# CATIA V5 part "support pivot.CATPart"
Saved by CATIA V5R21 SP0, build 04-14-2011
Part number: SupportPivot
Bounding box of the stored display mesh (mm): x -21 to 21, y -21 to 38, z 0 to 27
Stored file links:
  C:\Users\2027.DESARCY-LEMIE30\Desktop\V14(17.02.2023)\support pivot.CATPart
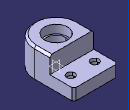
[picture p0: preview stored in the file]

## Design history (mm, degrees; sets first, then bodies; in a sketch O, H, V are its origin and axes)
Body1 (main body)
  Sketch1 on xy-plane, origin (0, 0, 0), H (1, 0, 0), V (0, 1, 0)
    arc A1 centre (0, 0) radius 21 from (-21, 0) to (21, 0) ccw
    line L1 (-21, 15) -> (21, 15)
    line L2 (21, 15) -> (21, 0)
    line L3 (-21, 0) -> (-21, 15)
    radius A1 = 21
    length L1 = 42
    distance L1 H = 15
    horizontal: L1 H
    vertical: L2 V, L3 V
  Pad1: profile Sketch1, direction (0, 0, 1), length 27
  Sketch2 on xy-plane, origin (0, 0, 0), H (1, 0, 0), V (0, 1, 0)
    line L1 (21, 0) -> (21, 38)
    line L2 (21, 38) -> (-21, 38)
    line L3 (-21, 38) -> (-21, 0)
    line L4 (-21, 0) -> (21, 0)
    distance L2 H = 38
    distance L1 V = 21
    length L2 = 42
    horizontal: L2 H, L4 H
    vertical: L1 V, L3 V
  Pad2: profile Sketch2, direction (0, 0, 1), length 11
  Sketch3 on end face of Pad1, origin (1.3571, -8.2844, 27), H (1, 0, 0), V (0, 1, 0)
    point P1 (-1.3571, 8.2844)
    reference projected arc E1 centre (-1.3571, 8.2844) radius 21 from (-22.3571, 8.2844) to (19.6429, 8.2844) ccw from edge [face of Pad1 from Sketch1.A1 | end face of Pad1]
    reference intersected line E2 through (-1.3571, 0) direction (0, 1) from yz-plane
    reference intersected line E3 through (0, 8.2844) direction (-1, 0) from zx-plane
    radius E1 = 21 (reference)
    distance P1 E2 = 0
    distance E3 P1 = 0
  Hole1: placed by Sketch3, at (0, 0, 27) direction (0, 0, -1), diameter 22, through (limit type 6)
  Sketch4 on face of Pad2, origin (-11.5216, 25.6596, 0), H (1, 0, 0), V (0, -1, 0)
    point P1 (0.0216, 0.1596)
    reference projected line E1 (-9.4784, 10.6596) -> (-9.4784, 25.6596) from edge [face of Pad2 | face of Pad2]
    reference projected line E2 (32.5216, -12.3404) -> (-9.4784, -12.3404) from edge [start face of Pad2 | face of Pad2 from Sketch2.L2]
    distance P1 E1 = 9.5
    distance P1 E2 = 12.5
  Hole2: placed by Sketch4, at (-11.5, 25.5, 0) direction (0, 0, 1), diameter 7.9, through (limit type 6), counterbore diameter 12.76, counterbore depth 8
  Sketch5 on face of Pad2, origin (12.0454, 25.2497, 0), H (1, 0, 0), V (0, -1, 0)
    point P1 (-0.5454, -0.2503)
    reference projected line E1 (8.9546, 25.2497) -> (8.9546, 10.2497) from edge [face of Pad2 | face of Pad2]
    reference projected line E2 (8.9546, -12.7503) -> (-33.0454, -12.7503) from edge [start face of Pad2 | face of Pad2 from Sketch2.L2]
    distance P1 E1 = 9.5
    distance P1 E2 = 12.5
  Hole3: placed by Sketch5, at (11.5, 25.5, 0) direction (0, 0, 1), diameter 7.9, through (limit type 6), counterbore diameter 12.76, counterbore depth 8
  Chamfer1: length 2, angle 45, on edge [face of Pad2 from Sketch2.L2 | face of Pad2]
  Chamfer2: length 2, angle 45, on edge [face of Pad1 from Sketch1.A1 | end face of Pad1]
  Chamfer3: length 2, angle 45, on edge [face of Pad2 | face of Pad2 from Sketch2.L2]
  Sketch6 on xy-plane, origin (0, 0, 0), H (1, 0, 0), V (0, 1, 0)
    circle A1 centre (0, 0) radius 9.5
    projected circle E1 centre (0, 0) radius 11 from edge [end face of Pad1 | face of Hole1]
    radius A1 = 9.5
  Pad3: profile Sketch6, direction (0, 0, 1), length 19, opposite side length -7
